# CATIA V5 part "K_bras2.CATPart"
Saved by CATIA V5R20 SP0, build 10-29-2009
Part number: bras2
Publications: "Plan.1", "Point.1", "Plan.2", "Plan.3", "Droite.1", "Plan.5", "Plan.4", "Point.3"
Bounding box of the stored display mesh (mm): x -8.994 to 111.999, y -91.997 to 23.992, z 166.555 to 186.555
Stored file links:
  G:\Khaled_CFAO_2011\SIL\SIL_GR2\pfradet\pfradet\Khaled\CAD_ThinkMOTION\K_bras2.CATPart
  U:\TNHIKMOTION\ass_cutting_device.CATProduct
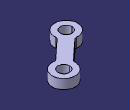
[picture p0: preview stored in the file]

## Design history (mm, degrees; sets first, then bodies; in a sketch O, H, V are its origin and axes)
Set1
  Plane1: linked copy from another document
  Point1: linked copy from another document
  Plane2: linked copy from another document
  Point2: linked copy from another document
Set2
  Plane3: type Offset, RefPlane Plane1, Offset 0
  Plane4: type Offset, RefPlane Plane2, Offset 0
  Line1: type Normal, RefPoint Point2, RefSkin Plane4, Start 0, End 60
  Plane5: type Offset, RefPlane Plane4, Offset 0
  Point3: type Center, Curve edge [end face of Pad1 | face of Pocket1 from Sketch2.A1]
  Point4: type Center, Curve Sketch1
Body1 (main body)
  Sketch1 on Plane3, origin (0, 0, 166.5555), H (1, 0, 0), V (0, 1, 0)
    arc A1 centre (15, -68) radius 24 from (20, -44.5266) to (38.4559, -62.9187) ccw
    arc A2 centre (88, 0) radius 24 from (81.896, -23.2108) to (64.3357, -4) ccw
    point P2 (88, 0)
    line L1 (20, -44.5266) -> (64.3357, -4)
    line L2 (81.896, -23.2108) -> (38.4559, -62.9187)
    coincidence: P2 H
    parallelism: L2 L1
  Pad1: profile Sketch1, direction (0, 0, 1), length 20
  Sketch2 on end face of Pad1, origin (0, 0, 186.5555), H (1, 0, 0), V (0, 1, 0)
    circle A1 centre (15, -68) radius 12
    reference projected arc E1 centre (15, -68) radius 24 from (20, -44.5266) to (38.4559, -62.9187) ccw from Sketch1.A1
    concentricity: A1 E1
  Pocket1: profile Sketch2, direction (0, 0, -1), length 20
  Sketch3 on end face of Pad1, origin (0, 0, 186.5555), H (1, 0, 0), V (0, 1, 0)
    circle A1 centre (88, 0) radius 12
    point P1 (88, 0)
    coincidence: P1 H
  Pocket2: profile Sketch3, direction (0, 0, -1), length 20
  Fillet1: radius 5, on edge [face of Pad1 from Sketch1.A1 | face of Pad1 from Sketch1.L1]
  Fillet2: radius 5, on edge [face of Pad1 from Sketch1.L1 | face of Pad1 from Sketch1.A2]
  Fillet3: radius 5, on edge [face of Pad1 from Sketch1.L2 | face of Pad1 from Sketch1.A1]
  Fillet4: radius 5, on edge [face of Pad1 from Sketch1.A2 | face of Pad1 from Sketch1.L2]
